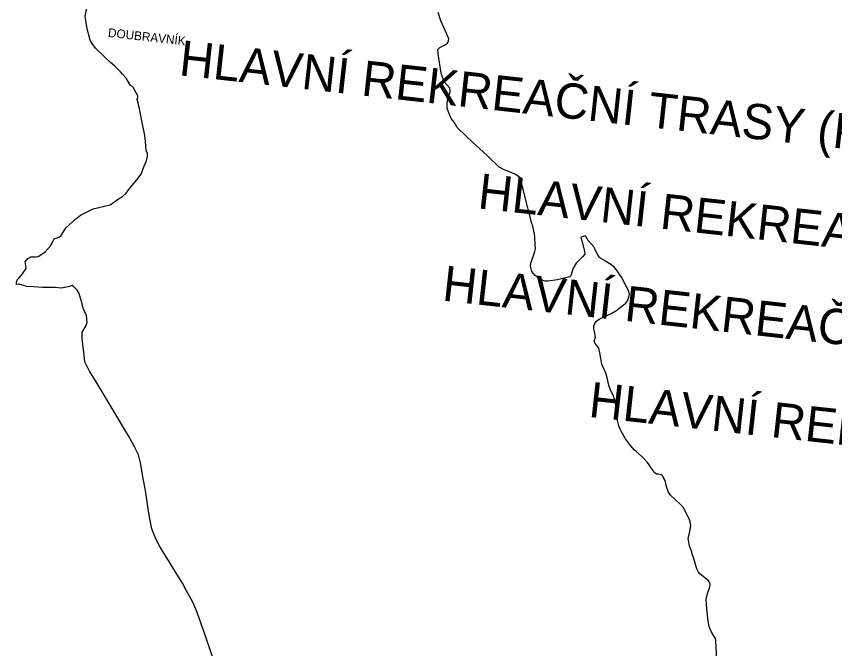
# Model space of a CAD drawing. Extents: x -678204 to -526855, y -1228851 to -1110393.
# Drawn here: x -613430 to -607858, y -1138582 to -1134277 of the extents above; entities that cross this region are included whole.
import ezdxf

# ---------------------------------------------------------------- set-up
doc = ezdxf.new("R2010")
doc.units = 0
for name, color, linetype in [('00_n_cyklo popisy detaily', 7, 'Continuous'), ('00_n_cyklo prujezdne rekreacni hlavni', 7, 'Continuous'), ('00_n_cyklo realizace rekreacni hlavni', 7, 'Continuous'), ('00_n_cyklo trasovani rekreacni hlavni', 7, 'Continuous'), ('00_n_legenda popisy', 7, 'Continuous'), ('trasy_0001', 7, 'Continuous')]:
    doc.layers.add(name, color=color, linetype=linetype)

msp = doc.modelspace()

# ---------------------------------------------------------------- linework, layer by layer
at = {"layer": '00_n_cyklo prujezdne rekreacni hlavni'}
for points in [[(-608658.9, -1138656.2), (-608666.2, -1138530.4), (-608668.5, -1138514.6), (-608695.5, -1138470.2), (-608705.3, -1138450.5), (-608712.5, -1138431.5), (-608718.6, -1138395.5), (-608728.9, -1138312.4), (-608732.4, -1138247.2), (-608723.9, -1138207.5), (-608710.4, -1138171.8), (-608705.6, -1138149.1), (-608708.3, -1138131.3), (-608718.5, -1138119.4), (-608775.4, -1138073.7), (-608785.4, -1138061.9), (-608791.4, -1138048), (-608795.7, -1138038.1), (-608798.8, -1138031.7), (-608816.8, -1137968.5), (-608825.4, -1137946.1), (-608830.9, -1137925.7), (-608845.6, -1137883), (-608853.8, -1137845.9), (-608855.6, -1137829.6), (-608851.8, -1137814.2), (-608841.4, -1137772.7), (-608837.8, -1137745.1), (-608840.9, -1137723.2), (-608841.5, -1137719.2), (-608845.5, -1137706.5), (-608849.8, -1137695.1), (-608854.5, -1137684.3), (-608890.4, -1137619.7), (-608915.2, -1137594.1), (-608939.6, -1137571.1), (-608976.7, -1137534.2), (-608990.7, -1137512.3), (-609002.4, -1137477.6), (-609011.2, -1137437.7), (-609024.7, -1137414.3), (-609030.7, -1137403.8), (-609039.1, -1137399.3), (-609059.4, -1137393.8), (-609071.4, -1137394.4), (-609083.2, -1137386.2), (-609109.4, -1137349), (-609116.2, -1137337), (-609131.2, -1137315.8), (-609159.3, -1137284.9), (-609170.5, -1137275.1), (-609212.1, -1137238.9), (-609221.4, -1137230.8), (-609248.6, -1137199.9), (-609281.2, -1137153.1), (-609309.8, -1137106.3), (-609317.5, -1137089), (-609327.9, -1137065.8), (-609339.6, -1137019.7), (-609343.7, -1136987.7), (-609348.8, -1136919.7), (-609354.5, -1136889.8), (-609363.5, -1136863.2), (-609368.7, -1136853), (-609384.1, -1136822.5), (-609396.5, -1136789.3), (-609398.3, -1136778.9), (-609407.5, -1136737.4), (-609413.7, -1136714.1), (-609416.9, -1136706.5), (-609436.5, -1136660.4), (-609443.4, -1136644.8), (-609456.9, -1136568.9), (-609464.2, -1136537.1), (-609489.2, -1136503.6), (-609493.1, -1136496.3), (-609495.5, -1136488.4), (-609486.5, -1136461.2), (-609488.7, -1136449.4), (-609491.8, -1136433.5), (-609498.8, -1136404.1), (-609498.2, -1136383.5), (-609491.1, -1136368.2), (-609479.7, -1136353.2), (-609461.9, -1136338.3), (-609447.8, -1136331.2), (-609374.6, -1136299.1), (-609348.2, -1136282.5), (-609327.4, -1136266.8), (-609294.7, -1136242.2), (-609281.9, -1136232.5), (-609268.6, -1136215), (-609257.8, -1136180.7), (-609255, -1136171.8), (-609259.3, -1136148.4), (-609275.6, -1136117.8), (-609310.3, -1136052.9), (-609342.5, -1136002.7), (-609357.8, -1135987.4), (-609374, -1135971.1), (-609430.3, -1135937.4), (-609449.6, -1135926.7), (-609457.8, -1135919.4), (-609471, -1135902), (-609491.4, -1135859.4), (-609497.4, -1135847), (-609535.5, -1135804.3), (-609554.9, -1135771.4), (-609585.4, -1135781.1), (-609575.5, -1135821.3), (-609561.4, -1135879), (-609559, -1135895.4), (-609574.2, -1135913.6), (-609617.4, -1135956.9), (-609639.6, -1135996.8), (-609655.1, -1136044.4), (-609661, -1136050.3), (-609745.7, -1136071.1), (-609810, -1136080.1), (-609829, -1136081), (-609849.7, -1136073.6), (-609897.1, -1136042.1), (-609919.2, -1136014.4), (-609928.1, -1135978.7), (-609926.7, -1135956.9), (-609900.1, -1135879), (-609895.3, -1135860.1), (-609896.1, -1135831.9), (-609898.4, -1135773.3), (-609912.8, -1135705), (-609920.2, -1135686.5), (-609971.7, -1135482.9), (-609976.6, -1135464), (-609994.2, -1135395.8), (-609996.4, -1135377.7), (-610013.1, -1135365.4), (-610040.6, -1135348.5), (-610087, -1135329.1), (-610113.8, -1135320.8), (-610141.5, -1135303.1), (-610223.2, -1135223.7), (-610327.2, -1135130.8), (-610366.3, -1135091.6), (-610427.5, -1135032.9), (-610449.2, -1134998.2), (-610468.4, -1134973.5), (-610490.6, -1134923.5), (-610496.2, -1134903.1), (-610497.2, -1134861.6), (-610475.8, -1134791), (-610479.5, -1134765.1), (-610518, -1134722.2), (-610537.6, -1134663.4), (-610558.4, -1134531.3), (-610559.6, -1134503.2), (-610546.1, -1134488.5), (-610514.3, -1134473.8), (-610493.5, -1134460.4), (-610488.6, -1134444.5), (-610485.9, -1134430), (-610498.4, -1134398), (-610538.8, -1134307.5), (-610557.4, -1134251.3)], [(-612949.6, -1136366.8), (-612948.7, -1136364.3), (-612953.9, -1136311.8), (-612972.5, -1136272.8), (-612982.5, -1136235.1), (-613002.2, -1136163.6), (-613016, -1136141), (-613038.2, -1136119.8), (-613051.1, -1136108.8), (-613068.8, -1136117.2), (-613122.6, -1136127.5), (-613166.7, -1136124.3), (-613252.1, -1136122.4), (-613314.5, -1136118.5), (-613359.6, -1136115.9), (-613388.9, -1136108.5), (-613411.2, -1136100.4), (-613428.9, -1136102.4), (-613430.5, -1136092.4), (-613424.7, -1136071.1), (-613412.1, -1136056.6), (-613388.9, -1136030.9), (-613364.5, -1135992.8), (-613366.7, -1135974.8), (-613371.5, -1135947.7), (-613351.6, -1135925.5), (-613331.9, -1135914.2), (-613295.9, -1135914.9), (-613278.5, -1135910.4), (-613233.7, -1135879.8), (-613198.6, -1135840.1), (-613181.7, -1135809.1), (-613172, -1135792.3), (-613153, -1135785.5), (-613136.9, -1135777.5), (-613125.7, -1135768.5), (-613092.5, -1135716.3), (-613027.8, -1135658), (-612994, -1135630.3), (-612908, -1135588.1), (-612792, -1135559.4), (-612736, -1135520.1), (-612707.7, -1135504), (-612681.6, -1135480.8), (-612657.7, -1135447.9), (-612610.7, -1135389.9), (-612579.5, -1135352.6), (-612563.4, -1135301), (-612545, -1135261.7), (-612536.7, -1135228.9), (-612538.3, -1135209.9), (-612545.7, -1135190.2), (-612550.2, -1135129.3), (-612555.3, -1135087.1), (-612578.8, -1134977.9), (-612591.1, -1134903.2), (-612608.1, -1134842.9), (-612603.9, -1134828.7), (-612603.2, -1134817.5), (-612638, -1134756.9), (-612652.5, -1134747.2), (-612683.1, -1134697.6), (-612706.9, -1134670.2), (-612721.7, -1134653.9), (-612736.6, -1134639.7)], [(-612187.3, -1138368.9), (-612195.9, -1138343.7), (-612204.9, -1138318.5), (-612230.7, -1138262.5), (-612271.6, -1138188.1), (-612299, -1138137.8), (-612348.9, -1138056.9), (-612394, -1137982.2), (-612426.2, -1137932.3), (-612450.3, -1137891.4), (-612481.2, -1137835.9), (-612507.3, -1137766.7), (-612523.7, -1137687.8), (-612532.4, -1137630.1), (-612552.1, -1137504.8), (-612566.9, -1137422.9), (-612584, -1137316.7), (-612598.8, -1137263.8), (-612625.2, -1137207.4), (-612661, -1137144.6), (-612784.3, -1136936.2), (-612880.3, -1136777.7), (-612933.1, -1136693.6), (-612963.4, -1136629.2), (-612971.4, -1136563.5), (-612982.8, -1136472.5), (-612981.6, -1136428.1), (-612955.5, -1136383), (-612949.6, -1136366.8)], [(-612057, -1138746.5), (-612106, -1138605.2), (-612145.7, -1138490.2), (-612170.1, -1138419.7), (-612187.3, -1138368.9)]]:
    msp.add_lwpolyline(points, dxfattribs=at)
at = {"layer": '00_n_cyklo realizace rekreacni hlavni'}
msp.add_lwpolyline([(-612736.6, -1134639.7), (-612762.6, -1134614.9), (-612789.6, -1134590.6), (-612820, -1134563.9), (-612843.3, -1134539.2), (-612891.6, -1134493.2), (-612914.9, -1134461.4), (-612927.4, -1134438), (-612940, -1134395.3), (-612949.7, -1134347.2), (-612960.9, -1134274.9), (-612952.8, -1134229.8), (-612939.6, -1134199.4), (-612916.6, -1134173.8), (-612892.8, -1134154.7), (-612857.9, -1134145.5), (-612843.2, -1134153.2), (-612837.8, -1134163.1), (-612835.4, -1134197.2), (-612829.8, -1134196.3)], dxfattribs=at)
at = {"layer": '00_n_cyklo trasovani rekreacni hlavni'}
for points in [[(-612736.6, -1134639.7), (-612762.6, -1134614.9), (-612789.6, -1134590.6), (-612820, -1134563.9), (-612843.3, -1134539.2), (-612891.6, -1134493.2), (-612914.9, -1134461.4), (-612927.4, -1134438), (-612940, -1134395.3), (-612949.7, -1134347.2), (-612960.9, -1134274.9), (-612952.8, -1134229.8), (-612939.6, -1134199.4), (-612916.6, -1134173.8), (-612892.8, -1134154.7), (-612857.9, -1134145.5), (-612843.2, -1134153.2), (-612837.8, -1134163.1), (-612835.4, -1134197.2), (-612829.8, -1134196.3)], [(-608658.9, -1138656.2), (-608666.2, -1138530.4), (-608668.5, -1138514.6), (-608695.5, -1138470.2), (-608705.3, -1138450.5), (-608712.5, -1138431.5), (-608718.6, -1138395.5), (-608728.9, -1138312.4), (-608732.4, -1138247.2), (-608723.9, -1138207.5), (-608710.4, -1138171.8), (-608705.6, -1138149.1), (-608708.3, -1138131.3), (-608718.5, -1138119.4), (-608775.4, -1138073.7), (-608785.4, -1138061.9), (-608791.4, -1138048), (-608795.7, -1138038.1), (-608798.8, -1138031.7), (-608816.8, -1137968.5), (-608825.4, -1137946.1), (-608830.9, -1137925.7), (-608845.6, -1137883), (-608853.8, -1137845.9), (-608855.6, -1137829.6), (-608851.8, -1137814.2), (-608841.4, -1137772.7), (-608837.8, -1137745.1), (-608840.9, -1137723.2), (-608841.5, -1137719.2), (-608845.5, -1137706.5), (-608849.8, -1137695.1), (-608854.5, -1137684.3), (-608890.4, -1137619.7), (-608915.2, -1137594.1), (-608939.6, -1137571.1), (-608976.7, -1137534.2), (-608990.7, -1137512.3), (-609002.4, -1137477.6), (-609011.2, -1137437.7), (-609024.7, -1137414.3), (-609030.7, -1137403.8), (-609039.1, -1137399.3), (-609059.4, -1137393.8), (-609071.4, -1137394.4), (-609083.2, -1137386.2), (-609109.4, -1137349), (-609116.2, -1137337), (-609131.2, -1137315.8), (-609159.3, -1137284.9), (-609170.5, -1137275.1), (-609212.1, -1137238.9), (-609221.4, -1137230.8), (-609248.6, -1137199.9), (-609281.2, -1137153.1), (-609309.8, -1137106.3), (-609317.5, -1137089), (-609327.9, -1137065.8), (-609339.6, -1137019.7), (-609343.7, -1136987.7), (-609348.8, -1136919.7), (-609354.5, -1136889.8), (-609363.5, -1136863.2), (-609368.7, -1136853), (-609384.1, -1136822.5), (-609396.5, -1136789.3), (-609398.3, -1136778.9), (-609407.5, -1136737.4), (-609413.7, -1136714.1), (-609416.9, -1136706.5), (-609436.5, -1136660.4), (-609443.4, -1136644.8), (-609456.9, -1136568.9), (-609464.2, -1136537.1), (-609489.2, -1136503.6), (-609493.1, -1136496.3), (-609495.5, -1136488.4), (-609486.5, -1136461.2), (-609488.7, -1136449.4), (-609491.8, -1136433.5), (-609498.8, -1136404.1), (-609498.2, -1136383.5), (-609491.1, -1136368.2), (-609479.7, -1136353.2), (-609461.9, -1136338.3), (-609447.8, -1136331.2), (-609374.6, -1136299.1), (-609348.2, -1136282.5), (-609327.4, -1136266.8), (-609294.7, -1136242.2), (-609281.9, -1136232.5), (-609268.6, -1136215), (-609257.8, -1136180.7), (-609255, -1136171.8), (-609259.3, -1136148.4), (-609275.6, -1136117.8), (-609310.3, -1136052.9), (-609342.5, -1136002.7), (-609357.8, -1135987.4), (-609374, -1135971.1), (-609430.3, -1135937.4), (-609449.6, -1135926.7), (-609457.8, -1135919.4), (-609471, -1135902), (-609491.4, -1135859.4), (-609497.4, -1135847), (-609535.5, -1135804.3), (-609554.9, -1135771.4), (-609585.4, -1135781.1), (-609575.5, -1135821.3), (-609561.4, -1135879), (-609559, -1135895.4), (-609574.2, -1135913.6), (-609617.4, -1135956.9), (-609639.6, -1135996.8), (-609655.1, -1136044.4), (-609661, -1136050.3), (-609745.7, -1136071.1), (-609810, -1136080.1), (-609829, -1136081), (-609849.7, -1136073.6), (-609897.1, -1136042.1), (-609919.2, -1136014.4), (-609928.1, -1135978.7), (-609926.7, -1135956.9), (-609900.1, -1135879), (-609895.3, -1135860.1), (-609896.1, -1135831.9), (-609898.4, -1135773.3), (-609912.8, -1135705), (-609920.2, -1135686.5), (-609971.7, -1135482.9), (-609976.6, -1135464), (-609994.2, -1135395.8), (-609996.4, -1135377.7), (-610013.1, -1135365.4), (-610040.6, -1135348.5), (-610087, -1135329.1), (-610113.8, -1135320.8), (-610141.5, -1135303.1), (-610223.2, -1135223.7), (-610327.2, -1135130.8), (-610366.3, -1135091.6), (-610427.5, -1135032.9), (-610449.2, -1134998.2), (-610468.4, -1134973.5), (-610490.6, -1134923.5), (-610496.2, -1134903.1), (-610497.2, -1134861.6), (-610475.8, -1134791), (-610479.5, -1134765.1), (-610518, -1134722.2), (-610537.6, -1134663.4), (-610558.4, -1134531.3), (-610559.6, -1134503.2), (-610546.1, -1134488.5), (-610514.3, -1134473.8), (-610493.5, -1134460.4), (-610488.6, -1134444.5), (-610485.9, -1134430), (-610498.4, -1134398), (-610538.8, -1134307.5), (-610557.4, -1134251.3)], [(-612949.6, -1136366.8), (-612948.7, -1136364.3), (-612953.9, -1136311.8), (-612972.5, -1136272.8), (-612982.5, -1136235.1), (-613002.2, -1136163.6), (-613016, -1136141), (-613038.2, -1136119.8), (-613051.1, -1136108.8), (-613068.8, -1136117.2), (-613122.6, -1136127.5), (-613166.7, -1136124.3), (-613252.1, -1136122.4), (-613314.5, -1136118.5), (-613359.6, -1136115.9), (-613388.9, -1136108.5), (-613411.2, -1136100.4), (-613428.9, -1136102.4), (-613430.5, -1136092.4), (-613424.7, -1136071.1), (-613412.1, -1136056.6), (-613388.9, -1136030.9), (-613364.5, -1135992.8), (-613366.7, -1135974.8), (-613371.5, -1135947.7), (-613351.6, -1135925.5), (-613331.9, -1135914.2), (-613295.9, -1135914.9), (-613278.5, -1135910.4), (-613233.7, -1135879.8), (-613198.6, -1135840.1), (-613181.7, -1135809.1), (-613172, -1135792.3), (-613153, -1135785.5), (-613136.9, -1135777.5), (-613125.7, -1135768.5), (-613092.5, -1135716.3), (-613027.8, -1135658), (-612994, -1135630.3), (-612908, -1135588.1), (-612792, -1135559.4), (-612736, -1135520.1), (-612707.7, -1135504), (-612681.6, -1135480.8), (-612657.7, -1135447.9), (-612610.7, -1135389.9), (-612579.5, -1135352.6), (-612563.4, -1135301), (-612545, -1135261.7), (-612536.7, -1135228.9), (-612538.3, -1135209.9), (-612545.7, -1135190.2), (-612550.2, -1135129.3), (-612555.3, -1135087.1), (-612578.8, -1134977.9), (-612591.1, -1134903.2), (-612608.1, -1134842.9), (-612603.9, -1134828.7), (-612603.2, -1134817.5), (-612638, -1134756.9), (-612652.5, -1134747.2), (-612683.1, -1134697.6), (-612706.9, -1134670.2), (-612721.7, -1134653.9), (-612736.6, -1134639.7)], [(-612187.3, -1138368.9), (-612195.9, -1138343.7), (-612204.9, -1138318.5), (-612230.7, -1138262.5), (-612271.6, -1138188.1), (-612299, -1138137.8), (-612348.9, -1138056.9), (-612394, -1137982.2), (-612426.2, -1137932.3), (-612450.3, -1137891.4), (-612481.2, -1137835.9), (-612507.3, -1137766.7), (-612523.7, -1137687.8), (-612532.4, -1137630.1), (-612552.1, -1137504.8), (-612566.9, -1137422.9), (-612584, -1137316.7), (-612598.8, -1137263.8), (-612625.2, -1137207.4), (-612661, -1137144.6), (-612784.3, -1136936.2), (-612880.3, -1136777.7), (-612933.1, -1136693.6), (-612963.4, -1136629.2), (-612971.4, -1136563.5), (-612982.8, -1136472.5), (-612981.6, -1136428.1), (-612955.5, -1136383), (-612949.6, -1136366.8)], [(-612057, -1138746.5), (-612106, -1138605.2), (-612145.7, -1138490.2), (-612170.1, -1138419.7), (-612187.3, -1138368.9)]]:
    msp.add_lwpolyline(points, dxfattribs=at)
at = {"layer": 'trasy_0001'}
msp.add_lwpolyline([(-608658.9, -1138656.2), (-608666.2, -1138530.4), (-608668.5, -1138514.6), (-608695.5, -1138470.2), (-608705.3, -1138450.5), (-608712.5, -1138431.5), (-608718.6, -1138395.5), (-608728.9, -1138312.4), (-608732.4, -1138247.2), (-608723.9, -1138207.5), (-608710.4, -1138171.8), (-608705.6, -1138149.1), (-608708.3, -1138131.3), (-608718.5, -1138119.4), (-608775.4, -1138073.7), (-608785.4, -1138061.9), (-608791.4, -1138048), (-608795.7, -1138038.1), (-608798.8, -1138031.7), (-608816.8, -1137968.5), (-608825.4, -1137946.1), (-608830.9, -1137925.7), (-608845.6, -1137883), (-608853.8, -1137845.9), (-608855.6, -1137829.6), (-608851.8, -1137814.2), (-608841.4, -1137772.7), (-608837.8, -1137745.1), (-608840.9, -1137723.2), (-608841.5, -1137719.2), (-608845.5, -1137706.5), (-608849.8, -1137695.1), (-608854.5, -1137684.3), (-608890.4, -1137619.7), (-608915.2, -1137594.1), (-608939.6, -1137571.1), (-608976.7, -1137534.2), (-608990.7, -1137512.3), (-609002.4, -1137477.6), (-609011.2, -1137437.7), (-609024.7, -1137414.3), (-609030.7, -1137403.8), (-609039.1, -1137399.3), (-609059.4, -1137393.8), (-609071.4, -1137394.4), (-609083.2, -1137386.2), (-609109.4, -1137349), (-609116.2, -1137337), (-609131.2, -1137315.8), (-609159.3, -1137284.9), (-609170.5, -1137275.1), (-609212.1, -1137238.9), (-609221.4, -1137230.8), (-609248.6, -1137199.9), (-609281.2, -1137153.1), (-609309.8, -1137106.3), (-609317.5, -1137089), (-609327.9, -1137065.8), (-609339.6, -1137019.7), (-609343.7, -1136987.7), (-609348.8, -1136919.7), (-609354.5, -1136889.8), (-609363.5, -1136863.2), (-609368.7, -1136853), (-609384.1, -1136822.5), (-609396.5, -1136789.3), (-609398.3, -1136778.9), (-609407.5, -1136737.4), (-609413.7, -1136714.1), (-609416.9, -1136706.5), (-609436.5, -1136660.4), (-609443.4, -1136644.8), (-609456.9, -1136568.9), (-609464.2, -1136537.1), (-609489.2, -1136503.6), (-609493.1, -1136496.3), (-609495.5, -1136488.4), (-609486.5, -1136461.2), (-609488.7, -1136449.4), (-609491.8, -1136433.5), (-609498.8, -1136404.1), (-609498.2, -1136383.5), (-609491.1, -1136368.2), (-609479.7, -1136353.2), (-609461.9, -1136338.3), (-609447.8, -1136331.2), (-609374.6, -1136299.1), (-609348.2, -1136282.5), (-609327.4, -1136266.8), (-609294.7, -1136242.2), (-609281.9, -1136232.5), (-609268.6, -1136215), (-609257.8, -1136180.7), (-609255, -1136171.8), (-609259.3, -1136148.4), (-609275.6, -1136117.8), (-609310.3, -1136052.9), (-609342.5, -1136002.7), (-609357.8, -1135987.4), (-609374, -1135971.1), (-609430.3, -1135937.4), (-609449.6, -1135926.7), (-609457.8, -1135919.4), (-609471, -1135902), (-609491.4, -1135859.4), (-609497.4, -1135847), (-609535.5, -1135804.3), (-609554.9, -1135771.4), (-609585.4, -1135781.1), (-609575.5, -1135821.3), (-609561.4, -1135879), (-609559, -1135895.4), (-609574.2, -1135913.6), (-609617.4, -1135956.9), (-609639.6, -1135996.8), (-609655.1, -1136044.4), (-609661, -1136050.3), (-609745.7, -1136071.1), (-609810, -1136080.1), (-609829, -1136081), (-609849.7, -1136073.6), (-609897.1, -1136042.1), (-609919.2, -1136014.4), (-609928.1, -1135978.7), (-609926.7, -1135956.9), (-609900.1, -1135879), (-609895.3, -1135860.1), (-609896.1, -1135831.9), (-609898.4, -1135773.3), (-609912.8, -1135705), (-609920.2, -1135686.5), (-609971.7, -1135482.9), (-609976.6, -1135464), (-609994.2, -1135395.8), (-609996.4, -1135377.7), (-610013.1, -1135365.4), (-610040.6, -1135348.5), (-610087, -1135329.1), (-610113.8, -1135320.8), (-610141.5, -1135303.1), (-610223.2, -1135223.7), (-610327.2, -1135130.8), (-610366.3, -1135091.6), (-610427.5, -1135032.9), (-610449.2, -1134998.2), (-610468.4, -1134973.5), (-610490.6, -1134923.5), (-610496.2, -1134903.1), (-610497.2, -1134861.6), (-610475.8, -1134791), (-610479.5, -1134765.1), (-610518, -1134722.2), (-610537.6, -1134663.4), (-610558.4, -1134531.3), (-610559.6, -1134503.2), (-610546.1, -1134488.5), (-610514.3, -1134473.8), (-610493.5, -1134460.4), (-610488.6, -1134444.5), (-610485.9, -1134430), (-610498.4, -1134398), (-610538.8, -1134307.5), (-610557.4, -1134251.3)], dxfattribs=at)

# ---------------------------------------------------------------- texts
at = {"layer": '00_n_cyklo popisy detaily'}
msp.add_text('DOUBRAVNÍK', height=60, rotation=353.6836, dxfattribs=at).set_placement((-612808.7, -1134416.5))
at = {"layer": '00_n_legenda popisy'}
for s, p in [('HLAVNÍ REKREAČNÍ TRASY (PODMÍNĚNĚ PRŮJEZDNÉ ÚSEKY K PROVĚŘENÍ) ', (-612328, -1134677.2)), ('HLAVNÍ REKREAČNÍ TRASY (NEPRŮJEZNÉ ÚSEKY K PROVĚŘENÍ) ', (-610293.8, -1135583.6)), ('HLAVNÍ REKREAČNÍ TRASY (PROJEKČNĚ PŘIPRAVOVANÉ ÚSEKY) ', (-610535.6, -1136211.8)), ('HLAVNÍ REKREAČNÍ TRASY (STUDIJNĚ PROVĚŘENÉ ÚSEKY) ', (-609538.4, -1137003.5))]:
    msp.add_text(s, height=240, rotation=353.6836, dxfattribs=at).set_placement(p)

doc.saveas('drawing.dxf')
